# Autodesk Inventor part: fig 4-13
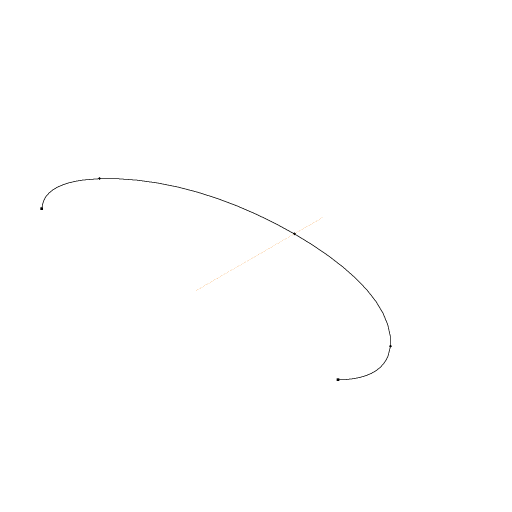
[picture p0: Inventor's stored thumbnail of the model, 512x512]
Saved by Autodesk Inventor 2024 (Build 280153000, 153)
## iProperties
Created: 2012-07
Part Number: fig 4-13
Material: Generic
Document SubType Name: Modeling
Designer: CADCIM
Density: 1 g/cm^3
Appearance: Default
Author: CADCIM
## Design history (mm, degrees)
sketch "Sketch1"
  geometry: L1 (0.121, 13.041)-(0.121, 1.483); L2 (-10.815, -1.576)-(-15.691, 3.573); L3 (-3.522, 10.439)-(3.764, 10.439); L4 (-14.873, 3.848)-(-11.149, 8.074); L5 (11.391, 8.074)-(15.115, 3.848); L6 (15.933, 3.573)-(11.057, -1.576); A1 r 5.401 centre (-9.332, 4.712) between (-14.53, 3.248) and (-11.076, -0.399); A2 r 30.439 centre (0.121, -20) between (3.022, 10.3) and (-2.78, 10.3); A3 r 7.63 centre (-7.286, 0.917) between (-11.348, 7.376) and (-14.205, 4.133); A4 r 7.63 centre (7.528, 0.917) between (14.447, 4.133) and (11.59, 7.376); A5 r 5.401 centre (9.574, 4.712) between (11.318, -0.399) and (14.772, 3.248); 5 further points
  constraints: 12 end point, 10 symmetric about line, 8 midpoint, 5 centre point, 5 point on circle, 1 vertical, 19 other
